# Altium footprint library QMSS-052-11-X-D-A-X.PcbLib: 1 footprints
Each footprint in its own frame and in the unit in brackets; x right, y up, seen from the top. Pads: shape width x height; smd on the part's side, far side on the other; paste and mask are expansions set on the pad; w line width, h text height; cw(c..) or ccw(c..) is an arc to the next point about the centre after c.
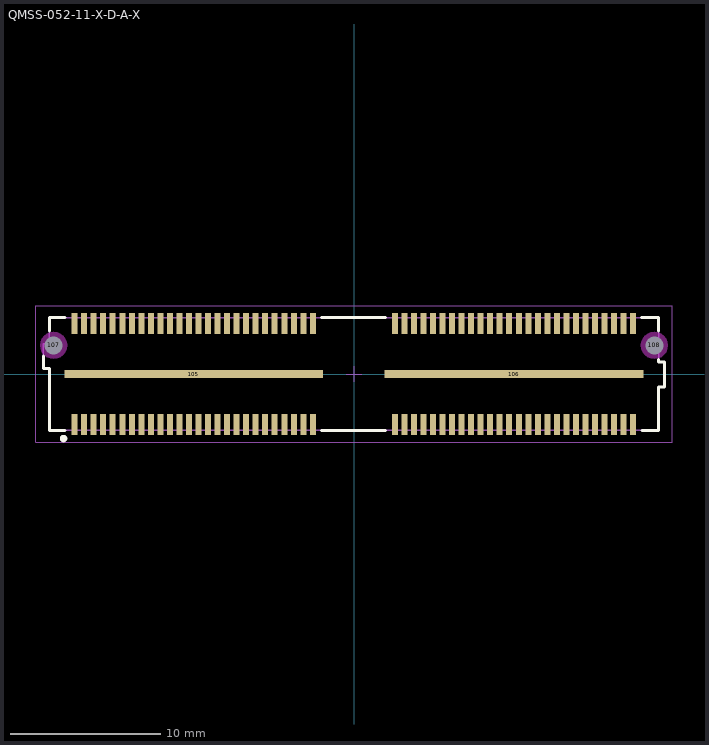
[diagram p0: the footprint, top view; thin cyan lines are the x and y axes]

## QMSS-052-11-X-D-A-X [mm] "0.635mm pitch, 104 pin, shielded header; w/2 banks, w/52 pins/bank, w/40 signals/bank, w/12 GND pin/bank"
height 6.35
pads (108):
  rect 0.4x1.4 smd mask+0: 1(-18.616,-3.365) 2(-18.616,3.365) 3(-17.981,-3.365) 4(-17.981,3.365) 5(-17.346,-3.365) 6(-17.346,3.365) 7(-16.711,-3.365) 8(-16.711,3.365) 9(-16.076,-3.365) 10(-16.076,3.365) 11(-15.441,-3.365) 12(-15.441,3.365) 13(-14.806,-3.365) 14(-14.806,3.365) 15(-14.171,-3.365) 16(-14.171,3.365) 17(-13.536,-3.365) 18(-13.536,3.365) 19(-12.901,-3.365) 20(-12.901,3.365) 21(-12.266,-3.365) 22(-12.266,3.365) 23(-11.631,-3.365) 24(-11.631,3.365) 25(-10.996,-3.365) 26(-10.996,3.365) 27(-10.361,-3.365) 28(-10.361,3.365) 29(-9.726,-3.365) 30(-9.726,3.365) 31(-9.091,-3.365) 32(-9.091,3.365) 33(-8.456,-3.365) 34(-8.456,3.365) 35(-7.821,-3.365) 36(-7.821,3.365) 37(-7.186,-3.365) 38(-7.186,3.365) 39(-6.551,-3.365) 40(-6.551,3.365) 41(-5.916,-3.365) 42(-5.916,3.365) 43(-5.281,-3.365) 44(-5.281,3.365) 45(-4.646,-3.365) 46(-4.646,3.365) 47(-4.011,-3.365) 48(-4.011,3.365) 49(-3.376,-3.365) 50(-3.376,3.365) 51(-2.741,-3.365) 52(-2.741,3.365) 53(2.724,-3.365) 54(2.724,3.365) 55(3.359,-3.365) 56(3.359,3.365) 57(3.994,-3.365) 58(3.994,3.365) 59(4.629,-3.365) 60(4.629,3.365) 61(5.264,-3.365) 62(5.264,3.365) 63(5.899,-3.365) 64(5.899,3.365) 65(6.534,-3.365) 66(6.534,3.365) 67(7.169,-3.365) 68(7.169,3.365) 69(7.804,-3.365) 70(7.804,3.365) 71(8.439,-3.365) 72(8.439,3.365) 73(9.074,-3.365) 74(9.074,3.365) 75(9.709,-3.365) 76(9.709,3.365) 77(10.344,-3.365) 78(10.344,3.365) 79(10.979,-3.365) 80(10.979,3.365) 81(11.614,-3.365) 82(11.614,3.365) 83(12.249,-3.365) 84(12.249,3.365) 85(12.884,-3.365) 86(12.884,3.365) 87(13.519,-3.365) 88(13.519,3.365) 89(14.154,-3.365) 90(14.154,3.365) 91(14.789,-3.365) 92(14.789,3.365) 93(15.424,-3.365) 94(15.424,3.365) 95(16.059,-3.365) 96(16.059,3.365) 97(16.694,-3.365) 98(16.694,3.365) 99(17.329,-3.365) 100(17.329,3.365) 101(17.964,-3.365) 102(17.964,3.365) 103(18.599,-3.365) 104(18.599,3.365)
  rect 17.25x0.5 smd mask+0: 105(-10.676,0) 106(10.664,0)
  round 1 hole 1.2 unplated mask+0: 107(-20.011,1.91) 108(20.011,1.91)
Top Overlay:
  circle w0.25: c-19.35,-4.3 r0.125
  lines w0.2: -20.7,1.2 -20.7,0.35 -20.3,0.35 -20.3,-3.75 -19.25,-3.75 ; -20.3,2.85 -20.3,3.75 -19.25,3.75 ; -2.15,-3.75 2.1,-3.75 ; -2.15,3.75 2.1,3.75 ; 19.15,3.75 20.3,3.75 20.3,2.85 ; 19.2,-3.75 20.3,-3.75 20.3,-0.85 20.7,-0.85 20.7,0.8 20.3,0.8 20.3,0.95
Keep-Out Layer:
  pour cut-out: 20.919,1.91 20.888,2.145 20.797,2.364 20.653,2.552 20.465,2.696 20.246,2.787 20.011,2.818 19.776,2.787 19.557,2.696 19.369,2.552 19.225,2.364 19.134,2.145 19.103,1.91 19.134,1.675 19.225,1.456 19.369,1.268 19.557,1.124 19.776,1.033 20.011,1.002 20.246,1.033 20.465,1.124 20.653,1.268 20.797,1.456 20.888,1.675
  pour cut-out: -19.103,1.91 -19.134,2.145 -19.225,2.364 -19.369,2.552 -19.557,2.696 -19.776,2.787 -20.011,2.818 -20.246,2.787 -20.465,2.696 -20.653,2.552 -20.797,2.364 -20.888,2.145 -20.919,1.91 -20.888,1.675 -20.797,1.456 -20.653,1.268 -20.465,1.124 -20.246,1.033 -20.011,1.002 -19.776,1.033 -19.557,1.124 -19.369,1.268 -19.225,1.456 -19.134,1.675
Mechanical 12:
  lines w0.001: -20.7,0.35 -20.7,2 -20.3,2 -20.3,3.75 20.3,3.75 20.3,0.8 20.7,0.8 20.7,-0.85 20.3,-0.85 20.3,-3.75 -20.3,-3.75 -20.3,0.35 -20.7,0.35
Mechanical 13:
  lines w0.1: -20.7,0.35 -20.7,2 -20.3,2 -20.3,3.75 20.3,3.75 20.3,0.8 20.7,0.8 20.7,-0.85 20.3,-0.85 20.3,-3.75 -20.3,-3.75 -20.3,0.35 -20.7,0.35
  text ".Designator" at 0.254,0.254 h1.52
Mechanical 15:
  lines w0.05: -0.5,0 0.5,0 ; 0,-0.5 0,0.5 ; -21.2,-4.55 -21.2,4.55 21.2,4.55 21.2,-4.55 -21.2,-4.55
